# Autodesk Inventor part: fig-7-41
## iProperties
Shininess: 77.0
Length Units: 11269
Angle Units: 11279
Time Units: 11290
Mass Units: 11283
Length Display Precision: 3
Angle Display Precision: 2
Created: 2002-01
Part Number: fig-7-41
Document SubType Name: Modeling
Designer: ***
Density: 1 g/cm^3
Density: 0.0
Volumn: 0.0
Area: 0.0
PropertySet Name: Model Information
Control State: 0
Master: False
Checked Out: False
Author: ***
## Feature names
1. Extrusion1
2. Fillet1
3. Extrusion2
4. Extrusion3
5. Chamfer1
